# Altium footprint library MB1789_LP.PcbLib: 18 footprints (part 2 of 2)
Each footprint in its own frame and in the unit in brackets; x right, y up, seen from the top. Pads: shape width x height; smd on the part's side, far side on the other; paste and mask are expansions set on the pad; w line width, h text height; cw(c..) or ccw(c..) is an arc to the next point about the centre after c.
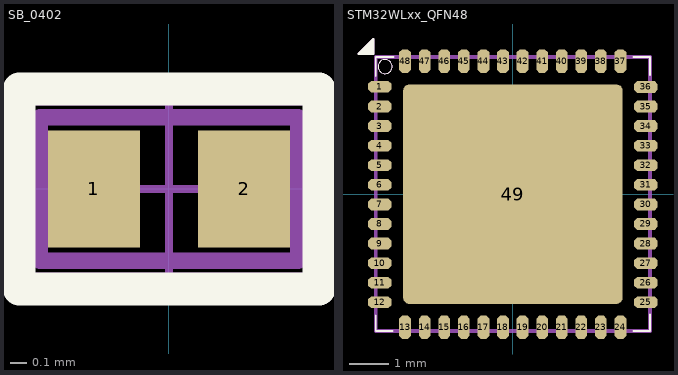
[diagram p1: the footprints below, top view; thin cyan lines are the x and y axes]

## SB_0402 [mm] "Solder Bridge 0 Ohm (0402)"
height 0.6
pads (2):
  rect 0.55x0.7 smd: 1(-0.45,0) 2(0.45,0)
Top Overlay:
  lines w0.2: -0.9,-0.6 0.9,-0.6 0.9,0.6 -0.9,0.6 -0.9,-0.6
Top Assembly (Mech14):
  lines w0.1: -0.775,-0.43 0.775,-0.43 0.775,0.43 -0.775,0.43 -0.775,-0.43
  text ".Designator" at -1.1,0.4 h1.25
Mechanical 17:
  lines w0.05: -0.5,0 0.5,0 ; 0,-0.5 0,0.5 ; -0.9,-0.525 0.9,-0.525 0.9,0.525 -0.9,0.525 -0.9,-0.525
3D body: height 0.25, standoff 0, extent -0.5,-0.25 0.5,0.25

## STM32WLxx_QFN48 [mm] "QFN48 7x7x0.55mm pitch 0.5mm"
height 0.55
pads (49):
  oct 0.6x0.3 smd mask+0.06: 1(-3.398,2.746) 2(-3.398,2.239) 3(-3.398,1.739) 4(-3.398,1.239) 5(-3.398,0.739) 6(-3.398,0.239) 7(-3.398,-0.261) 8(-3.398,-0.761) 9(-3.398,-1.261) 10(-3.398,-1.761) 11(-3.398,-2.261) 12(-3.398,-2.761) 25(3.398,-2.761) 26(3.398,-2.261) 27(3.398,-1.761) 28(3.398,-1.261) 29(3.398,-0.761) 30(3.398,-0.261) 31(3.398,0.239) 32(3.398,0.739) 33(3.398,1.239) 34(3.398,1.739) 35(3.398,2.239) 36(3.398,2.739)
  oct 0.3x0.6 smd mask+0.06: 13(-2.752,-3.399) 14(-2.252,-3.399) 15(-1.752,-3.399) 16(-1.252,-3.399) 17(-0.752,-3.399) 18(-0.252,-3.399) 19(0.248,-3.399) 20(0.748,-3.399) 21(1.248,-3.399) 22(1.748,-3.399) 23(2.248,-3.399) 24(2.748,-3.399) 37(2.748,3.399) 38(2.248,3.399) 39(1.748,3.399) 40(1.248,3.399) 41(0.748,3.399) 42(0.248,3.399) 43(-0.252,3.399) 44(-0.752,3.399) 45(-1.252,3.399) 46(-1.752,3.399) 47(-2.252,3.399) 48(-2.752,3.399)
  rrect5% 5.6x5.6 smd paste-3 mask+0.08: 49(0,0)
Top Overlay:
  circle w0.025: c-3.263,3.258 r0.18
  lines w0.025: -3.502,-3.103 -3.502,-3.499 -3.079,-3.499 ; -3.502,3.489 -3.502,3.501 ; 3.077,3.501 3.498,3.501 ; 3.498,-3.499 3.498,-3.067
  lines w0.05: -3.869,3.634 -3.565,3.634 ; -3.869,3.659 -3.565,3.659 ; -3.793,3.583 -3.607,3.785 ; -3.59,3.608 -3.895,3.608 ; -3.59,3.684 -3.692,3.684 -3.615,3.659 -3.59,3.735 -3.895,3.583 -3.59,3.583 -3.59,3.924 -3.844,3.634 -3.565,3.888 -3.819,3.608 -3.895,3.608 ; -3.502,-3.103 -3.502,-3.499 -3.079,-3.499 ; -3.502,3.019 -3.502,3.489 ; -3.502,3.501 -3.044,3.501 ; 3.077,-3.499 3.498,-3.499 3.498,-3.067 ; 3.077,3.501 3.498,3.501 3.498,3.044 ; -3.895,3.608 -3.565,3.964 ; -3.565,3.964 -3.946,3.583 -3.565,3.583 -3.565,3.964
Top Paste:
  rectangle: 1.091,1.064 2.541,2.514
  rectangle: -0.713,1.064 0.737,2.514
  rectangle: -2.493,1.064 -1.043,2.514
  rectangle: 1.092,-0.71 2.542,0.74
  rectangle: -0.712,-0.71 0.738,0.74
  rectangle: -2.492,-0.71 -1.042,0.74
  rectangle: -2.492,-2.488 -1.042,-1.038
  rectangle: -0.712,-2.488 0.738,-1.038
  rectangle: 1.092,-2.488 2.542,-1.038
Top Assembly (Mech14):
  circle w0.025: c-3.263,3.258 r0.18
  lines w0.05: -3.869,3.634 -3.565,3.634 ; -3.869,3.659 -3.565,3.659 ; -3.793,3.583 -3.607,3.785 ; -3.59,3.608 -3.895,3.608 ; -3.59,3.684 -3.692,3.684 -3.615,3.659 -3.59,3.735 -3.895,3.583 -3.59,3.583 -3.59,3.924 -3.844,3.634 -3.565,3.888 -3.819,3.608 -3.895,3.608 ; -3.895,3.608 -3.565,3.964 ; -3.565,3.964 -3.946,3.583 -3.565,3.583 -3.565,3.964
  lines w0.1: -3.502,-3.499 -3.502,-3.103 ; -3.502,-3.499 -3.502,-3.103 ; -3.502,-3.499 -3.079,-3.499 ; -3.502,-3.499 -3.079,-3.499 ; -3.502,-3.103 -3.502,3.489 -3.502,3.501 3.077,3.501 ; -3.079,-3.499 3.498,-3.499 ; 3.077,3.501 3.498,3.501 ; 3.077,3.501 3.498,3.501 ; 3.498,-3.499 3.498,-3.067 ; 3.498,-3.499 3.498,-3.067 ; 3.498,-3.067 3.498,3.501
  text ".Designator" at -3.004,3.971 h1.25
3D body "User Library-QFN48_7x7.step": height 0.78, standoff -0.02, extent -3.511,-3.509 3.509,3.511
